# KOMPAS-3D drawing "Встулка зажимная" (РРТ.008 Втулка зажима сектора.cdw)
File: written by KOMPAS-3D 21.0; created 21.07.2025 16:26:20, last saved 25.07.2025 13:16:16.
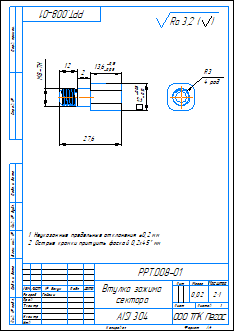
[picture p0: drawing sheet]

Sheet 1: A4, portrait

Document properties: Полное имя файла: ..\Модели КД\РРТ.008 Втулка зажима сектора.m3d; Автор: User; Знак неуказанной шероховатости: 4; Параметр неуказанной шероховатости: Ra 3,2; Масса: 0.01943

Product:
- Part/product: Встулка зажимная
    Масса: 0.01943
    Форматы листов документа: A4

Title block, sheet 1: Наименование: Втулка зажима / сектора; designation: РРТ.008-01; Материал: AISI 304; Масса: 0,02; Количество листов документа: 1; organisation: ООО ТПК Пегас; Форматы листов документа: A4; stored path: C:\Users\User\Desktop\Ручной ротатор КД\Чертежи\РРТ.008 Втулка зажимная сектора.cdw; Разработал: Гайсин

Views: Вид 1, Спереди, Проекционный вид 2
Referenced files in C:\Users\User\Desktop\Ручной ротатор КД\Модели КД\: РРТ.008 Встулка зажимная.m3d, РРТ.008 Втулка зажима сектора.m3d
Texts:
  Встулка зажимная
  Ra 3,2
  Ra 3,2 ( )
  Коническая винтовая линия (Внешняя цилиндрическая ступень с метрической резьбой):1
  Эскиз выреза профиля резьбы (Внешняя цилиндрическая ступень с метрической резьбой):1
  Эскиз для винтовой линии (Внешняя цилиндрическая ступень с метрической резьбой):1
Dimensions and other numbers on the sheet: 12; -7Н; 8; 2; 13,6; 27,6; 3; 4 рад; 2:1; 1; 0,02

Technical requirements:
  Неуказанные предельные отклонения  0,2 мм
  Острые кромки притуить фаской 0,2х45  мм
